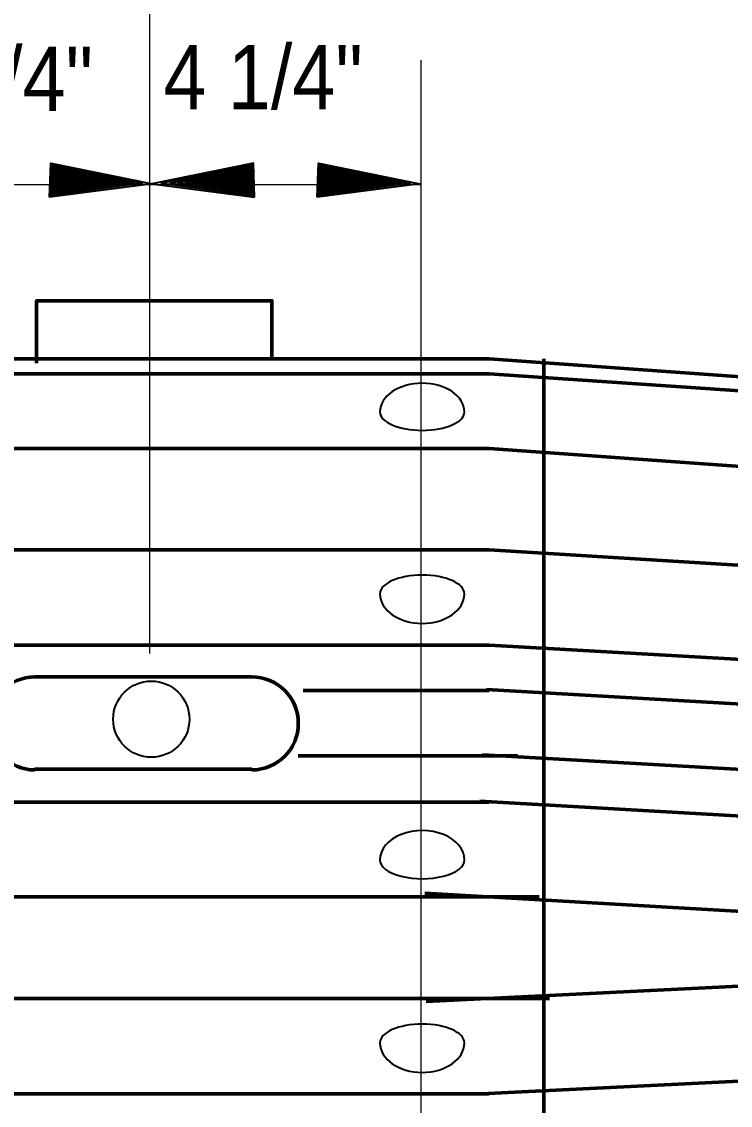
# Model space of a CAD drawing. Extents: x 895.6 to 930.4, y -2278.6 to -2254.7.
# Drawn here: x 912.917 to 914.335, y -2261.783 to -2259.614 of the extents above; entities that cross this region are included whole.
import ezdxf

# ---------------------------------------------------------------- set-up
doc = ezdxf.new("R2010")
doc.units = 0
doc.header["$LTSCALE"] = 0.051
doc.layers.add('1', color=7, linetype='Continuous', lineweight=70)
doc.layers.add('3', color=7, linetype='Continuous', lineweight=40)

msp = doc.modelspace()

# ---------------------------------------------------------------- hatches: boundary and pattern name
at = {"layer": '3'}
for points in [[(912.97233, -2259.96517), (912.97475, -2259.89683), (913.17817, -2259.93792), (913.17817, -2259.93792)], [(912.97333, -2259.96167), (912.97542, -2259.90025), (913.15858, -2259.93717), (913.15858, -2259.93717)], [(913.38292, -2259.96517), (913.38058, -2259.89683), (913.17717, -2259.93792), (913.17717, -2259.93792)], [(913.38192, -2259.96167), (913.37983, -2259.90025), (913.19675, -2259.93717), (913.19675, -2259.93717)], [(913.50817, -2259.96517), (913.51058, -2259.89683), (913.71392, -2259.93792), (913.71392, -2259.93792)], [(913.50917, -2259.96167), (913.51125, -2259.90025), (913.69433, -2259.93717), (913.69433, -2259.93717)], [(912.97425, -2259.95867), (912.97617, -2259.90342), (913.14092, -2259.93675), (913.14092, -2259.93675)], [(912.97517, -2259.95592), (912.97683, -2259.90625), (913.12525, -2259.93617), (913.12525, -2259.93617)], [(912.97583, -2259.95358), (912.97742, -2259.90883), (913.11092, -2259.93575), (913.11092, -2259.93575)], [(912.97675, -2259.95133), (912.97808, -2259.91092), (913.09817, -2259.93525), (913.09817, -2259.93525)], [(912.97725, -2259.94917), (912.97833, -2259.91292), (913.08658, -2259.93483), (913.08658, -2259.93483)], [(912.97783, -2259.94758), (912.97883, -2259.91483), (913.07608, -2259.93442), (913.07608, -2259.93442)], [(912.97817, -2259.94592), (912.97933, -2259.91642), (913.06683, -2259.93417), (913.06683, -2259.93417)], [(912.97875, -2259.94433), (912.97967, -2259.91783), (913.05842, -2259.93383), (913.05842, -2259.93383)], [(912.97917, -2259.94317), (912.97992, -2259.91925), (913.05083, -2259.93367), (913.05083, -2259.93367)], [(912.97942, -2259.94175), (912.98033, -2259.92067), (913.04408, -2259.93333), (913.04408, -2259.93333)], [(912.97983, -2259.94092), (912.98042, -2259.92158), (913.03783, -2259.93317), (913.03783, -2259.93317)], [(912.98033, -2259.93983), (912.98067, -2259.92258), (913.03242, -2259.93308), (913.03242, -2259.93308)], [(912.98042, -2259.93908), (912.98108, -2259.92342), (913.02742, -2259.93283), (913.02742, -2259.93283)], [(912.98067, -2259.93825), (912.98117, -2259.92417), (913.02292, -2259.93258), (913.02292, -2259.93258)], [(913.38108, -2259.95867), (913.37917, -2259.90342), (913.21433, -2259.93675), (913.21433, -2259.93675)], [(913.38017, -2259.95592), (913.37842, -2259.90625), (913.23008, -2259.93617), (913.23008, -2259.93617)], [(913.37942, -2259.95358), (913.37783, -2259.90883), (913.24433, -2259.93575), (913.24433, -2259.93575)], [(913.37858, -2259.95133), (913.37725, -2259.91092), (913.25717, -2259.93525), (913.25717, -2259.93525)], [(913.37808, -2259.94917), (913.37692, -2259.91292), (913.26875, -2259.93483), (913.26875, -2259.93483)], [(913.37742, -2259.94758), (913.37642, -2259.91483), (913.27925, -2259.93442), (913.27925, -2259.93442)], [(913.37717, -2259.94592), (913.37592, -2259.91642), (913.28842, -2259.93417), (913.28842, -2259.93417)], [(913.37658, -2259.94433), (913.37567, -2259.91783), (913.29683, -2259.93383), (913.29683, -2259.93383)], [(913.37617, -2259.94317), (913.37533, -2259.91925), (913.30442, -2259.93367), (913.30442, -2259.93367)], [(913.37583, -2259.94175), (913.37492, -2259.92067), (913.31125, -2259.93333), (913.31125, -2259.93333)], [(913.37542, -2259.94092), (913.37483, -2259.92158), (913.31742, -2259.93317), (913.31742, -2259.93317)], [(913.37492, -2259.93983), (913.37467, -2259.92258), (913.32283, -2259.93308), (913.32283, -2259.93308)], [(913.37483, -2259.93908), (913.37425, -2259.92342), (913.32783, -2259.93283), (913.32783, -2259.93283)], [(913.37467, -2259.93825), (913.37417, -2259.92417), (913.33233, -2259.93258), (913.33233, -2259.93258)], [(913.51008, -2259.95867), (913.51192, -2259.90342), (913.67675, -2259.93675), (913.67675, -2259.93675)], [(913.51092, -2259.95592), (913.51267, -2259.90625), (913.66108, -2259.93617), (913.66108, -2259.93617)], [(913.51167, -2259.95358), (913.51325, -2259.90883), (913.64675, -2259.93575), (913.64675, -2259.93575)], [(913.51258, -2259.95133), (913.51383, -2259.91092), (913.63392, -2259.93525), (913.63392, -2259.93525)], [(913.51308, -2259.94917), (913.51417, -2259.91292), (913.62233, -2259.93483), (913.62233, -2259.93483)], [(913.51367, -2259.94758), (913.51467, -2259.91483), (913.61183, -2259.93442), (913.61183, -2259.93442)], [(913.51392, -2259.94592), (913.51517, -2259.91642), (913.60267, -2259.93417), (913.60267, -2259.93417)], [(913.51458, -2259.94433), (913.51542, -2259.91783), (913.59425, -2259.93383), (913.59425, -2259.93383)], [(913.51492, -2259.94317), (913.51575, -2259.91925), (913.58667, -2259.93367), (913.58667, -2259.93367)], [(913.51525, -2259.94175), (913.51617, -2259.92067), (913.57983, -2259.93333), (913.57983, -2259.93333)], [(913.51567, -2259.94092), (913.51625, -2259.92158), (913.57367, -2259.93317), (913.57367, -2259.93317)], [(913.51617, -2259.93983), (913.51642, -2259.92258), (913.56825, -2259.93308), (913.56825, -2259.93308)], [(913.51625, -2259.93908), (913.51683, -2259.92342), (913.56325, -2259.93283), (913.56325, -2259.93283)], [(913.51642, -2259.93825), (913.51692, -2259.92417), (913.55875, -2259.93258), (913.55875, -2259.93258)], [(912.98092, -2259.93758), (912.98125, -2259.92475), (913.01908, -2259.93242), (913.01908, -2259.93242)], [(912.98117, -2259.93692), (912.98133, -2259.92558), (913.01542, -2259.93233), (913.01542, -2259.93233)], [(912.98125, -2259.93658), (912.98158, -2259.92625), (913.01217, -2259.93233), (913.01217, -2259.93233)], [(912.98142, -2259.93608), (912.98183, -2259.92675), (913.00933, -2259.93233), (913.00933, -2259.93233)], [(912.98175, -2259.93575), (912.98208, -2259.92725), (913.00675, -2259.93242), (913.00675, -2259.93242)], [(912.98175, -2259.93525), (912.98208, -2259.92783), (913.00433, -2259.93233), (913.00433, -2259.93233)], [(912.98192, -2259.93475), (912.98217, -2259.92808), (913.00225, -2259.93208), (913.00225, -2259.93208)], [(912.98208, -2259.93442), (912.98217, -2259.92867), (913.00025, -2259.93217), (913.00025, -2259.93217)], [(913.37433, -2259.93758), (913.37408, -2259.92475), (913.33625, -2259.93242), (913.33625, -2259.93242)], [(913.37417, -2259.93692), (913.37392, -2259.92558), (913.33983, -2259.93233), (913.33983, -2259.93233)], [(913.37408, -2259.93658), (913.37375, -2259.92625), (913.34317, -2259.93233), (913.34317, -2259.93233)], [(913.37383, -2259.93608), (913.37342, -2259.92675), (913.34592, -2259.93233), (913.34592, -2259.93233)], [(913.37358, -2259.93575), (913.37325, -2259.92725), (913.34858, -2259.93242), (913.34858, -2259.93242)], [(913.37358, -2259.93525), (913.37325, -2259.92783), (913.35092, -2259.93233), (913.35092, -2259.93233)], [(913.37333, -2259.93475), (913.37317, -2259.92808), (913.35308, -2259.93208), (913.35308, -2259.93208)], [(913.37325, -2259.93442), (913.37317, -2259.92867), (913.35508, -2259.93217), (913.35508, -2259.93217)], [(913.51675, -2259.93758), (913.51708, -2259.92475), (913.55483, -2259.93242), (913.55483, -2259.93242)], [(913.51692, -2259.93692), (913.51717, -2259.92558), (913.55125, -2259.93233), (913.55125, -2259.93233)], [(913.51708, -2259.93658), (913.51733, -2259.92625), (913.54792, -2259.93233), (913.54792, -2259.93233)], [(913.51725, -2259.93608), (913.51767, -2259.92675), (913.54517, -2259.93233), (913.54517, -2259.93233)], [(913.51758, -2259.93575), (913.51783, -2259.92725), (913.54258, -2259.93242), (913.54258, -2259.93242)], [(913.51758, -2259.93525), (913.51783, -2259.92783), (913.54017, -2259.93233), (913.54017, -2259.93233)], [(913.51775, -2259.93475), (913.51792, -2259.92808), (913.53808, -2259.93208), (913.53808, -2259.93208)], [(913.51783, -2259.93442), (913.51792, -2259.92867), (913.53608, -2259.93217), (913.53608, -2259.93217)]]:
    msp.add_hatch(color=256, dxfattribs=at).paths.add_polyline_path(points)

# ---------------------------------------------------------------- linework, layer by layer
at = {"layer": '1', "lineweight": 25}
for p, q in [((913.17308, -2260.87842), (913.17308, -2258.93908)), ((913.71608, -2263.01075), (913.71608, -2259.69075)), ((912.12067, -2259.93958), (913.71608, -2259.93958))]:
    msp.add_line(p, q, dxfattribs=at)
at = {"layer": '1'}
for p, q in [((913.85217, -2260.28858), (912.43592, -2260.28858)), ((913.85217, -2260.28858), (921.30733, -2260.82175)), ((913.96208, -2262.65542), (913.96208, -2260.28858)), ((912.43625, -2260.31833), (913.85217, -2260.31833)), ((913.85217, -2260.31833), (921.30483, -2260.82608)), ((913.85217, -2260.46825), (912.43592, -2260.46825)), ((913.85217, -2260.46825), (921.30733, -2260.99608)), ((913.85217, -2260.67058), (912.43592, -2260.67058)), ((917.41958, -2260.88975), (913.85217, -2260.67058)), ((913.85217, -2260.86133), (912.43592, -2260.86133)), ((917.37925, -2261.06158), (913.85217, -2260.86133)), ((913.37733, -2260.92492), (912.94233, -2260.92492)), ((913.85217, -2260.95208), (913.47992, -2260.95208)), ((913.84792, -2260.95208), (913.47992, -2260.95208)), ((921.30733, -2261.37642), (913.84675, -2260.95042)), ((913.85217, -2261.08342), (913.47025, -2261.08342)), ((913.91008, -2261.08342), (913.47667, -2261.08342)), ((921.09808, -2261.49383), (913.83925, -2261.08083)), ((912.94233, -2261.10983), (913.37733, -2261.10983)), ((913.85217, -2261.17567), (912.43592, -2261.17567)), ((919.33525, -2261.48833), (913.83358, -2261.17408)), ((913.95217, -2261.36533), (912.43592, -2261.36533)), ((915.76767, -2261.47558), (913.72358, -2261.35817)), ((915.76767, -2261.47558), (913.72642, -2261.57492)), ((919.33525, -2261.48833), (913.83642, -2261.75992)), ((913.97317, -2261.56875), (912.43592, -2261.56875)), ((913.85217, -2261.75992), (912.43592, -2261.75992))]:
    msp.add_line(p, q, dxfattribs=at)
at = {"layer": '1', "lineweight": 13}
msp.add_line((913.91008, -2261.17567), (913.34992, -2261.17567), dxfattribs=at)
at = {"layer": '1'}
msp.add_lwpolyline([(912.94658, -2260.29683), (912.94658, -2260.17225), (913.41742, -2260.17225), (913.41742, -2260.28833)], dxfattribs=at)
at = {"layer": '1', "lineweight": 40}
msp.add_circle((913.17611, -2261.00973), 0.07627, dxfattribs=at)
at = {"layer": '1'}
for centre, start, end in [((912.94323, -2261.01826), 90, 270), ((913.37737, -2261.01826), 270, 90)]:
    msp.add_arc(centre, 0.09303, start, end, dxfattribs=at)
at = {"layer": '1', "lineweight": 40}
for centre, major_axis, ratio, start_param, end_param in [((913.71839, -2260.39484), (-0.08469, 0), 0.679978, 3.1415927, 6.2831853), ((913.71839, -2260.39484), (0.08469, 0), 0.434256, 3.1415927, 6.2831853), ((913.71839, -2260.75892), (-0.08469, 0), 0.442883, 3.1415927, 6.2831853), ((913.71839, -2260.75892), (0.08469, 0), 0.696674, 3.1415927, 6.2831853), ((913.71839, -2261.29156), (0.08469, 0), 0.696674, 6.2831853, 9.424778), ((913.71839, -2261.29156), (-0.08469, 0), 0.442883, 6.2831853, 9.424778), ((913.71839, -2261.65764), (-0.08469, 0), 0.442883, 3.1415927, 6.2831853), ((913.71839, -2261.65764), (0.08469, 0), 0.696674, 3.1415927, 6.2831853)]:
    msp.add_ellipse(centre, major_axis=major_axis, ratio=ratio, start_param=start_param, end_param=end_param, dxfattribs=at)
at = {"layer": '3'}
for points in [[(912.97233, -2259.96517), (912.97475, -2259.89683), (913.17817, -2259.93792), (913.17817, -2259.93792)], [(912.97333, -2259.96167), (912.97542, -2259.90025), (913.15858, -2259.93717), (913.15858, -2259.93717)], [(913.38292, -2259.96517), (913.38058, -2259.89683), (913.17717, -2259.93792), (913.17717, -2259.93792)], [(913.38192, -2259.96167), (913.37983, -2259.90025), (913.19675, -2259.93717), (913.19675, -2259.93717)], [(913.50817, -2259.96517), (913.51058, -2259.89683), (913.71392, -2259.93792), (913.71392, -2259.93792)], [(913.50917, -2259.96167), (913.51125, -2259.90025), (913.69433, -2259.93717), (913.69433, -2259.93717)], [(912.97425, -2259.95867), (912.97617, -2259.90342), (913.14092, -2259.93675), (913.14092, -2259.93675)], [(912.97517, -2259.95592), (912.97683, -2259.90625), (913.12525, -2259.93617), (913.12525, -2259.93617)], [(912.97583, -2259.95358), (912.97742, -2259.90883), (913.11092, -2259.93575), (913.11092, -2259.93575)], [(912.97675, -2259.95133), (912.97808, -2259.91092), (913.09817, -2259.93525), (913.09817, -2259.93525)], [(912.97725, -2259.94917), (912.97833, -2259.91292), (913.08658, -2259.93483), (913.08658, -2259.93483)], [(912.97783, -2259.94758), (912.97883, -2259.91483), (913.07608, -2259.93442), (913.07608, -2259.93442)], [(912.97817, -2259.94592), (912.97933, -2259.91642), (913.06683, -2259.93417), (913.06683, -2259.93417)], [(912.97875, -2259.94433), (912.97967, -2259.91783), (913.05842, -2259.93383), (913.05842, -2259.93383)], [(912.97917, -2259.94317), (912.97992, -2259.91925), (913.05083, -2259.93367), (913.05083, -2259.93367)], [(912.97942, -2259.94175), (912.98033, -2259.92067), (913.04408, -2259.93333), (913.04408, -2259.93333)], [(912.97983, -2259.94092), (912.98042, -2259.92158), (913.03783, -2259.93317), (913.03783, -2259.93317)], [(912.98033, -2259.93983), (912.98067, -2259.92258), (913.03242, -2259.93308), (913.03242, -2259.93308)], [(912.98042, -2259.93908), (912.98108, -2259.92342), (913.02742, -2259.93283), (913.02742, -2259.93283)], [(912.98067, -2259.93825), (912.98117, -2259.92417), (913.02292, -2259.93258), (913.02292, -2259.93258)], [(913.38108, -2259.95867), (913.37917, -2259.90342), (913.21433, -2259.93675), (913.21433, -2259.93675)], [(913.38017, -2259.95592), (913.37842, -2259.90625), (913.23008, -2259.93617), (913.23008, -2259.93617)], [(913.37942, -2259.95358), (913.37783, -2259.90883), (913.24433, -2259.93575), (913.24433, -2259.93575)], [(913.37858, -2259.95133), (913.37725, -2259.91092), (913.25717, -2259.93525), (913.25717, -2259.93525)], [(913.37808, -2259.94917), (913.37692, -2259.91292), (913.26875, -2259.93483), (913.26875, -2259.93483)], [(913.37742, -2259.94758), (913.37642, -2259.91483), (913.27925, -2259.93442), (913.27925, -2259.93442)], [(913.37717, -2259.94592), (913.37592, -2259.91642), (913.28842, -2259.93417), (913.28842, -2259.93417)], [(913.37658, -2259.94433), (913.37567, -2259.91783), (913.29683, -2259.93383), (913.29683, -2259.93383)], [(913.37617, -2259.94317), (913.37533, -2259.91925), (913.30442, -2259.93367), (913.30442, -2259.93367)], [(913.37583, -2259.94175), (913.37492, -2259.92067), (913.31125, -2259.93333), (913.31125, -2259.93333)], [(913.37542, -2259.94092), (913.37483, -2259.92158), (913.31742, -2259.93317), (913.31742, -2259.93317)], [(913.37492, -2259.93983), (913.37467, -2259.92258), (913.32283, -2259.93308), (913.32283, -2259.93308)], [(913.37483, -2259.93908), (913.37425, -2259.92342), (913.32783, -2259.93283), (913.32783, -2259.93283)], [(913.37467, -2259.93825), (913.37417, -2259.92417), (913.33233, -2259.93258), (913.33233, -2259.93258)], [(913.51008, -2259.95867), (913.51192, -2259.90342), (913.67675, -2259.93675), (913.67675, -2259.93675)], [(913.51092, -2259.95592), (913.51267, -2259.90625), (913.66108, -2259.93617), (913.66108, -2259.93617)], [(913.51167, -2259.95358), (913.51325, -2259.90883), (913.64675, -2259.93575), (913.64675, -2259.93575)], [(913.51258, -2259.95133), (913.51383, -2259.91092), (913.63392, -2259.93525), (913.63392, -2259.93525)], [(913.51308, -2259.94917), (913.51417, -2259.91292), (913.62233, -2259.93483), (913.62233, -2259.93483)], [(913.51367, -2259.94758), (913.51467, -2259.91483), (913.61183, -2259.93442), (913.61183, -2259.93442)], [(913.51392, -2259.94592), (913.51517, -2259.91642), (913.60267, -2259.93417), (913.60267, -2259.93417)], [(913.51458, -2259.94433), (913.51542, -2259.91783), (913.59425, -2259.93383), (913.59425, -2259.93383)], [(913.51492, -2259.94317), (913.51575, -2259.91925), (913.58667, -2259.93367), (913.58667, -2259.93367)], [(913.51525, -2259.94175), (913.51617, -2259.92067), (913.57983, -2259.93333), (913.57983, -2259.93333)], [(913.51567, -2259.94092), (913.51625, -2259.92158), (913.57367, -2259.93317), (913.57367, -2259.93317)], [(913.51617, -2259.93983), (913.51642, -2259.92258), (913.56825, -2259.93308), (913.56825, -2259.93308)], [(913.51625, -2259.93908), (913.51683, -2259.92342), (913.56325, -2259.93283), (913.56325, -2259.93283)], [(913.51642, -2259.93825), (913.51692, -2259.92417), (913.55875, -2259.93258), (913.55875, -2259.93258)], [(912.98092, -2259.93758), (912.98125, -2259.92475), (913.01908, -2259.93242), (913.01908, -2259.93242)], [(912.98117, -2259.93692), (912.98133, -2259.92558), (913.01542, -2259.93233), (913.01542, -2259.93233)], [(912.98125, -2259.93658), (912.98158, -2259.92625), (913.01217, -2259.93233), (913.01217, -2259.93233)], [(912.98142, -2259.93608), (912.98183, -2259.92675), (913.00933, -2259.93233), (913.00933, -2259.93233)], [(912.98175, -2259.93575), (912.98208, -2259.92725), (913.00675, -2259.93242), (913.00675, -2259.93242)], [(912.98175, -2259.93525), (912.98208, -2259.92783), (913.00433, -2259.93233), (913.00433, -2259.93233)], [(912.98192, -2259.93475), (912.98217, -2259.92808), (913.00225, -2259.93208), (913.00225, -2259.93208)], [(912.98208, -2259.93442), (912.98217, -2259.92867), (913.00025, -2259.93217), (913.00025, -2259.93217)], [(913.37433, -2259.93758), (913.37408, -2259.92475), (913.33625, -2259.93242), (913.33625, -2259.93242)], [(913.37417, -2259.93692), (913.37392, -2259.92558), (913.33983, -2259.93233), (913.33983, -2259.93233)], [(913.37408, -2259.93658), (913.37375, -2259.92625), (913.34317, -2259.93233), (913.34317, -2259.93233)], [(913.37383, -2259.93608), (913.37342, -2259.92675), (913.34592, -2259.93233), (913.34592, -2259.93233)], [(913.37358, -2259.93575), (913.37325, -2259.92725), (913.34858, -2259.93242), (913.34858, -2259.93242)], [(913.37358, -2259.93525), (913.37325, -2259.92783), (913.35092, -2259.93233), (913.35092, -2259.93233)], [(913.37333, -2259.93475), (913.37317, -2259.92808), (913.35308, -2259.93208), (913.35308, -2259.93208)], [(913.37325, -2259.93442), (913.37317, -2259.92867), (913.35508, -2259.93217), (913.35508, -2259.93217)], [(913.51675, -2259.93758), (913.51708, -2259.92475), (913.55483, -2259.93242), (913.55483, -2259.93242)], [(913.51692, -2259.93692), (913.51717, -2259.92558), (913.55125, -2259.93233), (913.55125, -2259.93233)], [(913.51708, -2259.93658), (913.51733, -2259.92625), (913.54792, -2259.93233), (913.54792, -2259.93233)], [(913.51725, -2259.93608), (913.51767, -2259.92675), (913.54517, -2259.93233), (913.54517, -2259.93233)], [(913.51758, -2259.93575), (913.51783, -2259.92725), (913.54258, -2259.93242), (913.54258, -2259.93242)], [(913.51758, -2259.93525), (913.51783, -2259.92783), (913.54017, -2259.93233), (913.54017, -2259.93233)], [(913.51775, -2259.93475), (913.51792, -2259.92808), (913.53808, -2259.93208), (913.53808, -2259.93208)], [(913.51783, -2259.93442), (913.51792, -2259.92867), (913.53608, -2259.93217), (913.53608, -2259.93217)]]:
    msp.add_lwpolyline(points, close=True, dxfattribs=at)

# ---------------------------------------------------------------- texts
at = {"layer": '1', "width": 0.9}
for p in [(912.66033, -2259.79233), (913.20033, -2259.78883)]:
    msp.add_text('4 1/4"', height=0.1286, dxfattribs=at).set_placement(p)

doc.saveas('drawing.dxf')
